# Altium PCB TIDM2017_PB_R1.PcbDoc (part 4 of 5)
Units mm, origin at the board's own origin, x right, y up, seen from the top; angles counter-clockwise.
Board outline 120 x 147.5 mm, 4 copper layers (Top Layer, L2, L3, Bottom Layer), stack 1.413 mm thick; 117 components, 53 nets, 3137 pads, 96 vias.
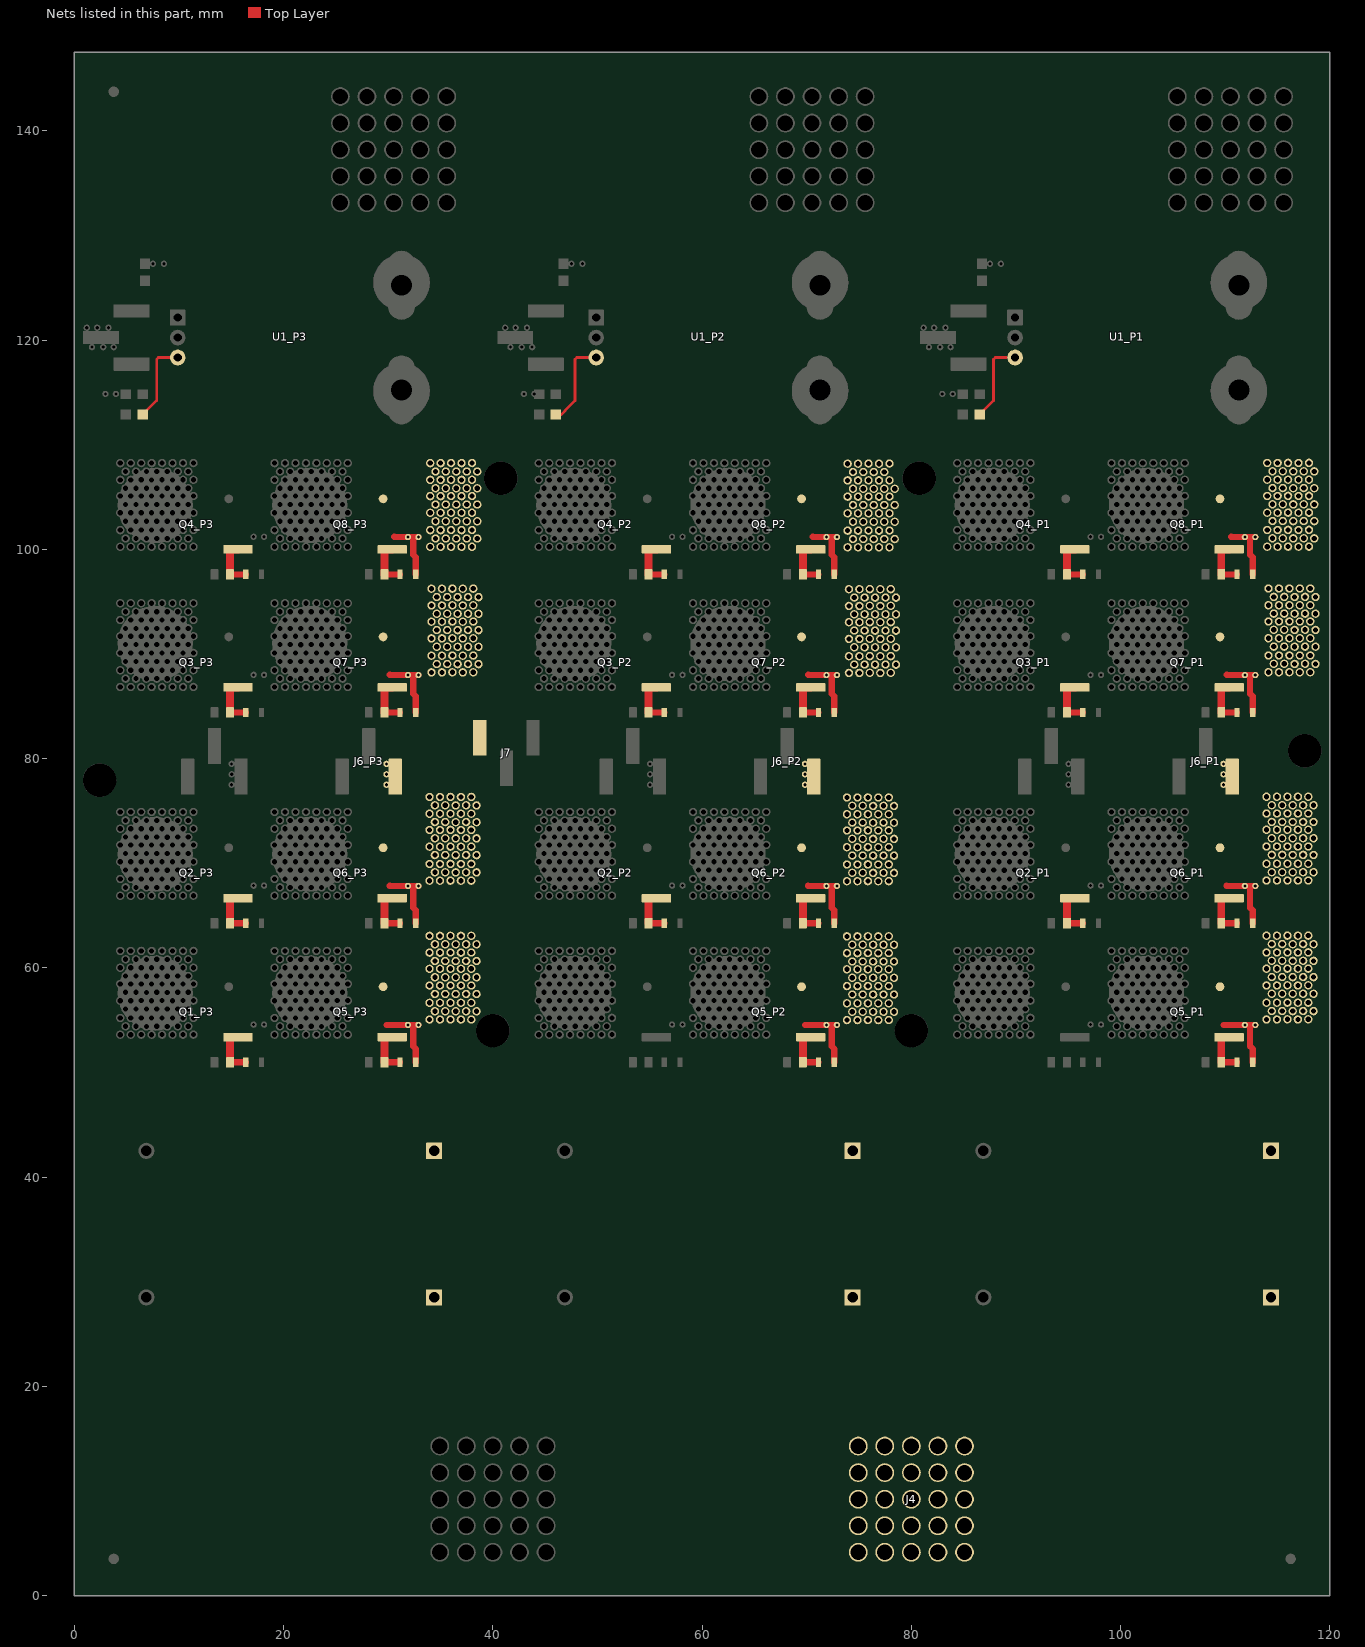
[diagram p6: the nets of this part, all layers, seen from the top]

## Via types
v1: diameter 0.8, hole 0.5, Top Layer to Bottom Layer, 96 vias

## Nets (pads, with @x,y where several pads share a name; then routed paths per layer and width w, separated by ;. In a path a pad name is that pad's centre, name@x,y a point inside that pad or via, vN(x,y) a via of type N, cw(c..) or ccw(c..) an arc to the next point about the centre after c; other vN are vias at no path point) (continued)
NetQ1_P3_1: Q1_P3.1 R1_P3.2 R5_P3.2 | length 4.6
  Top Layer w0.6: R1_P3.2@14.876,50.975 R5_P3.2@16.376,50.975
  Top Layer w0.75: R1_P3.2@14.876,50.975 14.876,53.347 14.901,53.372 Q1_P3.1@15.626,53.372
NetQ2_P1_1: Q2_P1.1 R2_P1.2 R6_P1.2 | length 4.6
  Top Layer w0.6: R2_P1.2@94.876,64.258 R6_P1.2@96.376,64.258
  Top Layer w0.75: R2_P1.2@94.876,64.258 94.876,66.63 94.901,66.655 Q2_P1.1@95.626,66.655
NetQ2_P2_1: Q2_P2.1 R2_P2.2 R6_P2.2 | length 4.6
  Top Layer w0.6: R2_P2.2@54.876,64.258 R6_P2.2@56.376,64.258
  Top Layer w0.75: R2_P2.2@54.876,64.258 54.876,66.63 54.901,66.655 Q2_P2.1@55.626,66.655
NetQ2_P3_1: Q2_P3.1 R2_P3.2 R6_P3.2 | length 4.6
  Top Layer w0.6: R2_P3.2@14.876,64.258 R6_P3.2@16.376,64.258
  Top Layer w0.75: R2_P3.2@14.876,64.258 14.876,66.63 14.901,66.655 Q2_P3.1@15.626,66.655
NetQ3_P1_1: Q3_P1.1 R3_P1.2 R7_P1.2 | length 4.6
  Top Layer w0.6: R3_P1.2@94.876,84.411 R7_P1.2@96.376,84.411
  Top Layer w0.75: R3_P1.2@94.876,84.411 94.876,86.783 94.901,86.808 Q3_P1.1@95.626,86.808
NetQ3_P2_1: Q3_P2.1 R3_P2.2 R7_P2.2 | length 4.6
  Top Layer w0.6: R3_P2.2@54.876,84.411 R7_P2.2@56.376,84.411
  Top Layer w0.75: R3_P2.2@54.876,84.411 54.876,86.783 54.901,86.808 Q3_P2.1@55.626,86.808
NetQ3_P3_1: Q3_P3.1 R3_P3.2 R7_P3.2 | length 4.6
  Top Layer w0.6: R3_P3.2@14.876,84.411 R7_P3.2@16.376,84.411
  Top Layer w0.75: R3_P3.2@14.876,84.411 14.876,86.783 14.901,86.808 Q3_P3.1@15.626,86.808
NetQ4_P1_1: Q4_P1.1 R4_P1.2 R8_P1.2 | length 4.6
  Top Layer w0.6: R4_P1.2@94.876,97.606 R8_P1.2@96.376,97.606
  Top Layer w0.75: R4_P1.2@94.876,97.606 94.876,99.978 94.901,100.003 Q4_P1.1@95.626,100.003
NetQ4_P2_1: Q4_P2.1 R4_P2.2 R8_P2.2 | length 4.6
  Top Layer w0.6: R4_P2.2@54.876,97.606 R8_P2.2@56.376,97.606
  Top Layer w0.75: R4_P2.2@54.876,97.606 54.876,99.978 54.901,100.003 Q4_P2.1@55.626,100.003
NetQ4_P3_1: Q4_P3.1 R4_P3.2 R8_P3.2 | length 4.6
  Top Layer w0.6: R4_P3.2@14.876,97.606 R8_P3.2@16.376,97.606
  Top Layer w0.75: R4_P3.2@14.876,97.606 14.876,99.978 14.901,100.003 Q4_P3.1@15.626,100.003
NetQ5_P1_1: Q5_P1.1 R9_P1.2 R13_P1.2 | length 4.6
  Top Layer w0.6: R9_P1.2@109.626,50.975 R13_P1.2@111.126,50.975
  Top Layer w0.75: R9_P1.2@109.626,50.975 109.626,53.347 109.651,53.372 Q5_P1.1@110.376,53.372
NetQ5_P2_1: Q5_P2.1 R9_P2.2 R13_P2.2 | length 4.6
  Top Layer w0.6: R9_P2.2@69.626,50.975 R13_P2.2@71.126,50.975
  Top Layer w0.75: R9_P2.2@69.626,50.975 69.626,53.347 69.651,53.372 Q5_P2.1@70.376,53.372
NetQ5_P3_1: Q5_P3.1 R9_P3.2 R13_P3.2 | length 4.6
  Top Layer w0.6: R9_P3.2@29.626,50.975 R13_P3.2@31.126,50.975
  Top Layer w0.75: R9_P3.2@29.626,50.975 29.626,53.347 29.651,53.372 Q5_P3.1@30.376,53.372
NetQ6_P1_1: Q6_P1.1 R10_P1.2 R14_P1.2 | length 4.6
  Top Layer w0.6: R10_P1.2@109.626,64.258 R14_P1.2@111.126,64.258
  Top Layer w0.75: R10_P1.2@109.626,64.258 109.626,66.63 109.651,66.655 Q6_P1.1@110.376,66.655
NetQ6_P2_1: Q6_P2.1 R10_P2.2 R14_P2.2 | length 4.6
  Top Layer w0.6: R10_P2.2@69.626,64.258 R14_P2.2@71.126,64.258
  Top Layer w0.75: R10_P2.2@69.626,64.258 69.626,66.63 69.651,66.655 Q6_P2.1@70.376,66.655
NetQ6_P3_1: Q6_P3.1 R10_P3.2 R14_P3.2 | length 4.6
  Top Layer w0.6: R10_P3.2@29.626,64.258 R14_P3.2@31.126,64.258
  Top Layer w0.75: R10_P3.2@29.626,64.258 29.626,66.63 29.651,66.655 Q6_P3.1@30.376,66.655
NetQ7_P1_1: Q7_P1.1 R11_P1.2 R15_P1.2 | length 4.6
  Top Layer w0.6: R11_P1.2@109.626,84.411 R15_P1.2@111.126,84.411
  Top Layer w0.75: R11_P1.2@109.626,84.411 109.626,86.783 109.651,86.808 Q7_P1.1@110.376,86.808
NetQ7_P2_1: Q7_P2.1 R11_P2.2 R15_P2.2 | length 4.6
  Top Layer w0.6: R11_P2.2@69.626,84.411 R15_P2.2@71.126,84.411
  Top Layer w0.75: R11_P2.2@69.626,84.411 69.626,86.783 69.651,86.808 Q7_P2.1@70.376,86.808
NetQ7_P3_1: Q7_P3.1 R11_P3.2 R15_P3.2 | length 4.6
  Top Layer w0.6: R11_P3.2@29.626,84.411 R15_P3.2@31.126,84.411
  Top Layer w0.75: R11_P3.2@29.626,84.411 29.626,86.783 29.651,86.808 Q7_P3.1@30.376,86.808
NetQ8_P1_1: Q8_P1.1 R12_P1.2 R16_P1.2 | length 4.6
  Top Layer w0.6: R12_P1.2@109.626,97.606 R16_P1.2@111.126,97.606
  Top Layer w0.75: R12_P1.2@109.626,97.606 109.626,99.978 109.651,100.003 Q8_P1.1@110.376,100.003
NetQ8_P2_1: Q8_P2.1 R12_P2.2 R16_P2.2 | length 4.6
  Top Layer w0.6: R12_P2.2@69.626,97.606 R16_P2.2@71.126,97.606
  Top Layer w0.75: R12_P2.2@69.626,97.606 69.626,99.978 69.651,100.003 Q8_P2.1@70.376,100.003
NetQ8_P3_1: Q8_P3.1 R12_P3.2 R16_P3.2 | length 4.6
  Top Layer w0.6: R12_P3.2@29.626,97.606 R16_P3.2@31.126,97.606
  Top Layer w0.75: R12_P3.2@29.626,97.606 29.626,99.978 29.651,100.003 Q8_P3.1@30.376,100.003
NetR17_P1_2: R17_P1.2 U1_P1.3 | length 7.2
  Top Layer w0.25: R17_P1.2@86.52,112.886 86.545,112.886 86.895,113.236 86.895,113.261 87.85,114.216 87.85,118.167 88.023,118.34 89.092,118.34
NetR17_P2_2: R17_P2.2 U1_P2.3 | length 7.2
  Top Layer w0.25: 46.52,112.886 46.545,112.886 46.895,113.236 46.895,113.261 47.85,114.216 47.85,118.167 48.023,118.34 49.092,118.34
NetR17_P3_2: R17_P3.2 U1_P3.3 | length 7.2
  Top Layer w0.25: R17_P3.2@6.52,112.886 6.545,112.886 6.895,113.236 6.895,113.261 7.85,114.216 7.85,118.167 8.023,118.34 9.092,118.34
S_LS_P1: C1_P1.1 C1_P2.1 C1_P3.1 C2_P1.1 C2_P2.1 C2_P3.1 J4.1 J6_P1.1 J6_P2.1 J6_P3.1 J7.1 pad.2@29.826,77.5 pad.2@29.826,78.5 pad.2@29.826,79.5 pad.2@31.876,54.547 pad.2@31.876,67.83 pad.2@31.876,87.983 pad.2@31.876,101.178 pad.2@32.876,54.547 pad.2@32.876,67.83 pad.2@32.876,87.983 pad.2@32.876,101.178 pad.2@33.939,55.054 pad.2@33.939,56.654 pad.2@33.939,58.304 pad.2@33.939,59.904 pad.2@33.939,61.457 pad.2@33.939,63.057 pad.2@33.939,68.332 pad.2@33.939,69.932 pad.2@33.939,71.582 pad.2@33.939,73.182 pad.2@33.939,74.735 pad.2@33.939,76.335 pad.2@34.001,100.242 pad.2@34.001,101.842 pad.2@34.001,103.492 pad.2@34.001,105.092 pad.2@34.001,106.644 pad.2@34.001,108.244 pad.2@34.126,88.242 pad.2@34.126,89.842 pad.2@34.126,91.492 pad.2@34.126,93.092 pad.2@34.126,94.644 pad.2@34.126,96.244 pad.2@34.452,55.852 pad.2@34.452,57.502 pad.2@34.452,59.102 pad.2@34.452,60.655 pad.2@34.452,62.255 pad.2@34.452,69.13 pad.2@34.452,70.78 pad.2@34.452,72.38 pad.2@34.452,73.933 pad.2@34.452,75.533 pad.2@34.514,101.04 pad.2@34.514,102.69 pad.2@34.514,104.29 pad.2@34.514,105.843 pad.2@34.514,107.443 pad.2@34.639,89.04 pad.2@34.639,90.69 pad.2@34.639,92.29 pad.2@34.639,93.843 pad.2@34.639,95.443 pad.2@34.939,55.054 pad.2@34.939,56.654 pad.2@34.939,58.304 pad.2@34.939,59.904 pad.2@34.939,61.457 pad.2@34.939,63.057 pad.2@34.939,68.332 pad.2@34.939,69.932 pad.2@34.939,71.582 pad.2@34.939,73.182 pad.2@34.939,74.735 pad.2@34.939,76.335 pad.2@35.001,100.242 pad.2@35.001,101.842 pad.2@35.001,103.492 pad.2@35.001,105.092 pad.2@35.001,106.644 pad.2@35.001,108.244 pad.2@35.126,88.242 pad.2@35.126,89.842 pad.2@35.126,91.492 pad.2@35.126,93.092 pad.2@35.126,94.644 pad.2@35.126,96.244 pad.2@35.439,55.852 pad.2@35.439,57.502 pad.2@35.439,59.102 pad.2@35.439,60.655 pad.2@35.439,62.255 pad.2@35.439,69.13 pad.2@35.439,70.78 pad.2@35.439,72.38 pad.2@35.439,73.933 pad.2@35.439,75.533 pad.2@35.501,101.04 pad.2@35.501,102.69 pad.2@35.501,104.29 pad.2@35.501,105.843 pad.2@35.501,107.443 pad.2@35.626,89.04 pad.2@35.626,90.69 pad.2@35.626,92.29 pad.2@35.626,93.843 pad.2@35.626,95.443 pad.2@35.939,55.059 pad.2@35.939,56.659 pad.2@35.939,58.309 pad.2@35.939,59.909 pad.2@35.939,61.462 pad.2@35.939,63.062 pad.2@35.939,68.337 pad.2@35.939,69.937 pad.2@35.939,71.587 pad.2@35.939,73.187 pad.2@35.939,74.74 pad.2@35.939,76.34 pad.2@36.001,100.247 pad.2@36.001,101.847 pad.2@36.001,103.497 pad.2@36.001,105.097 pad.2@36.001,106.65 pad.2@36.001,108.25 pad.2@36.126,88.247 pad.2@36.126,89.847 pad.2@36.126,91.497 pad.2@36.126,93.097 pad.2@36.126,94.65 pad.2@36.126,96.25 pad.2@36.439,55.847 pad.2@36.439,57.497 pad.2@36.439,59.097 pad.2@36.439,60.649 pad.2@36.439,62.249 pad.2@36.439,69.125 pad.2@36.439,70.775 pad.2@36.439,72.375 pad.2@36.439,73.927 pad.2@36.439,75.527 pad.2@36.501,101.035 pad.2@36.501,102.685 pad.2@36.501,104.285 pad.2@36.501,105.837 pad.2@36.501,107.437 pad.2@36.626,89.035 pad.2@36.626,90.685 pad.2@36.626,92.285 pad.2@36.626,93.837 pad.2@36.626,95.437 pad.2@36.939,55.054 pad.2@36.939,56.654 pad.2@36.939,58.304 pad.2@36.939,59.904 pad.2@36.939,61.457 pad.2@36.939,63.057 pad.2@36.939,68.332 pad.2@36.939,69.932 pad.2@36.939,71.582 pad.2@36.939,73.182 pad.2@36.939,74.735 pad.2@36.939,76.335 pad.2@37.001,100.242 pad.2@37.001,101.842 pad.2@37.001,103.492 pad.2@37.001,105.092 pad.2@37.001,106.644 pad.2@37.001,108.244 pad.2@37.126,88.242 pad.2@37.126,89.842 pad.2@37.126,91.492 pad.2@37.126,93.092 pad.2@37.126,94.644 pad.2@37.126,96.244 pad.2@37.439,55.852 pad.2@37.439,57.502 pad.2@37.439,59.102 pad.2@37.439,60.655 pad.2@37.439,62.255 pad.2@37.439,69.13 pad.2@37.439,70.78 pad.2@37.439,72.38 pad.2@37.439,73.933 pad.2@37.439,75.533 pad.2@37.501,101.04 pad.2@37.501,102.69 pad.2@37.501,104.29 pad.2@37.501,105.843 pad.2@37.501,107.443 pad.2@37.626,89.04 pad.2@37.626,90.69 pad.2@37.626,92.29 pad.2@37.626,93.843 pad.2@37.626,95.443 pad.2@37.939,55.059 pad.2@37.939,56.659 pad.2@37.939,58.309 pad.2@37.939,59.909 pad.2@37.939,61.462 pad.2@37.939,63.062 pad.2@37.939,68.337 pad.2@37.939,69.937 pad.2@37.939,71.587 pad.2@37.939,73.187 pad.2@37.939,74.74 pad.2@37.939,76.34 pad.2@38.001,100.247 pad.2@38.001,101.847 pad.2@38.001,103.497 pad.2@38.001,105.097 pad.2@38.001,106.65 pad.2@38.001,108.25 pad.2@38.126,88.247 pad.2@38.126,89.847 pad.2@38.126,91.497 pad.2@38.126,93.097 pad.2@38.126,94.65 pad.2@38.126,96.25 pad.2@38.439,55.847 pad.2@38.439,57.497 pad.2@38.439,59.097 pad.2@38.439,60.649 pad.2@38.439,62.249 pad.2@38.439,69.125 pad.2@38.439,70.775 pad.2@38.439,72.375 pad.2@38.439,73.927 pad.2@38.439,75.527 pad.2@38.501,101.035 pad.2@38.501,102.685 pad.2@38.501,104.285 pad.2@38.501,105.837 pad.2@38.501,107.437 pad.2@38.626,89.035 pad.2@38.626,90.685 pad.2@38.626,92.285 pad.2@38.626,93.837 pad.2@38.626,95.437 pad.2@69.826,77.5 pad.2@69.826,78.5 pad.2@69.826,79.5 pad.2@71.876,54.547 pad.2@71.876,67.83 pad.2@71.876,87.983 pad.2@71.876,101.178 pad.2@72.876,54.547 pad.2@72.876,67.83 pad.2@72.876,87.983 pad.2@72.876,101.178 pad.2@73.842,55.005 pad.2@73.842,56.605 pad.2@73.842,58.255 pad.2@73.842,59.855 pad.2@73.842,61.408 pad.2@73.842,63.008 pad.2@73.842,68.283 pad.2@73.842,69.883 pad.2@73.842,71.533 pad.2@73.842,73.133 pad.2@73.842,74.686 pad.2@73.842,76.286 pad.2@73.904,100.193 pad.2@73.904,101.793 pad.2@73.904,103.443 pad.2@73.904,105.043 pad.2@73.904,106.596 pad.2@73.904,108.196 pad.2@74.029,88.193 pad.2@74.029,89.793 pad.2@74.029,91.443 pad.2@74.029,93.043 pad.2@74.029,94.596 pad.2@74.029,96.196 pad.2@74.355,55.804 pad.2@74.355,57.454 pad.2@74.355,59.054 pad.2@74.355,60.606 pad.2@74.355,62.206 pad.2@74.355,69.082 pad.2@74.355,70.732 pad.2@74.355,72.332 pad.2@74.355,73.884 pad.2@74.355,75.484 pad.2@74.417,100.992 pad.2@74.417,102.642 pad.2@74.417,104.242 pad.2@74.417,105.794 pad.2@74.417,107.394 pad.2@74.542,88.992 pad.2@74.542,90.642 pad.2@74.542,92.242 pad.2@74.542,93.794 pad.2@74.542,95.394 pad.2@74.842,55.005 pad.2@74.842,56.605 pad.2@74.842,58.255 pad.2@74.842,59.855 pad.2@74.842,61.408 pad.2@74.842,63.008 pad.2@74.842,68.283 pad.2@74.842,69.883 pad.2@74.842,71.533 pad.2@74.842,73.133 pad.2@74.842,74.686 pad.2@74.842,76.286 pad.2@74.904,100.193 pad.2@74.904,101.793 pad.2@74.904,103.443 pad.2@74.904,105.043 pad.2@74.904,106.596 pad.2@74.904,108.196 pad.2@75.029,88.193 pad.2@75.029,89.793 pad.2@75.029,91.443 pad.2@75.029,93.043 pad.2@75.029,94.596 pad.2@75.029,96.196 pad.2@75.342,55.804 pad.2@75.342,57.454 pad.2@75.342,59.054 pad.2@75.342,60.606 pad.2@75.342,62.206 pad.2@75.342,69.082 pad.2@75.342,70.732 pad.2@75.342,72.332 pad.2@75.342,73.884 pad.2@75.342,75.484 pad.2@75.404,100.992 pad.2@75.404,102.642 pad.2@75.404,104.242 pad.2@75.404,105.794 pad.2@75.404,107.394 pad.2@75.529,88.992 pad.2@75.529,90.642 pad.2@75.529,92.242 pad.2@75.529,93.794 pad.2@75.529,95.394 pad.2@75.842,55.011 pad.2@75.842,56.611 pad.2@75.842,58.261 pad.2@75.842,59.861 pad.2@75.842,61.414 pad.2@75.842,63.014 pad.2@75.842,68.289 pad.2@75.842,69.889 pad.2@75.842,71.539 pad.2@75.842,73.139 pad.2@75.842,74.692 pad.2@75.842,76.292 pad.2@75.904,100.199 pad.2@75.904,101.799 pad.2@75.904,103.449 pad.2@75.904,105.049 pad.2@75.904,106.602 pad.2@75.904,108.202 pad.2@76.029,88.199 pad.2@76.029,89.799 pad.2@76.029,91.449 pad.2@76.029,93.049 pad.2@76.029,94.602 pad.2@76.029,96.202 pad.2@76.342,55.798 pad.2@76.342,57.448 pad.2@76.342,59.048 pad.2@76.342,60.601 pad.2@76.342,62.201 pad.2@76.342,69.076 pad.2@76.342,70.726 pad.2@76.342,72.326 pad.2@76.342,73.879 pad.2@76.342,75.479 pad.2@76.404,100.986 pad.2@76.404,102.636 pad.2@76.404,104.236 pad.2@76.404,105.789 pad.2@76.404,107.389 pad.2@76.529,88.986 pad.2@76.529,90.636 pad.2@76.529,92.236 pad.2@76.529,93.789 pad.2@76.529,95.389 pad.2@76.842,55.005 pad.2@76.842,56.605 pad.2@76.842,58.255 pad.2@76.842,59.855 pad.2@76.842,61.408 pad.2@76.842,63.008 pad.2@76.842,68.283 pad.2@76.842,69.883 pad.2@76.842,71.533 pad.2@76.842,73.133 pad.2@76.842,74.686 pad.2@76.842,76.286 pad.2@76.904,100.193 pad.2@76.904,101.793 pad.2@76.904,103.443 pad.2@76.904,105.043 pad.2@76.904,106.596 pad.2@76.904,108.196 pad.2@77.029,88.193 pad.2@77.029,89.793 pad.2@77.029,91.443 pad.2@77.029,93.043 pad.2@77.029,94.596 pad.2@77.029,96.196 pad.2@77.342,55.804 pad.2@77.342,57.454 pad.2@77.342,59.054 pad.2@77.342,60.606 pad.2@77.342,62.206 pad.2@77.342,69.082 pad.2@77.342,70.732 pad.2@77.342,72.332 pad.2@77.342,73.884 pad.2@77.342,75.484 pad.2@77.404,100.992 pad.2@77.404,102.642 pad.2@77.404,104.242 pad.2@77.404,105.794 pad.2@77.404,107.394 pad.2@77.529,88.992 pad.2@77.529,90.642 pad.2@77.529,92.242 pad.2@77.529,93.794 pad.2@77.529,95.394 pad.2@77.842,55.011 pad.2@77.842,56.611 pad.2@77.842,58.261 pad.2@77.842,59.861 pad.2@77.842,61.414 pad.2@77.842,63.014 pad.2@77.842,68.289 pad.2@77.842,69.889 pad.2@77.842,71.539 pad.2@77.842,73.139 pad.2@77.842,74.692 pad.2@77.842,76.292 pad.2@77.904,100.199 pad.2@77.904,101.799 pad.2@77.904,103.449 pad.2@77.904,105.049 pad.2@77.904,106.602 pad.2@77.904,108.202 pad.2@78.029,88.199 pad.2@78.029,89.799 pad.2@78.029,91.449 pad.2@78.029,93.049 pad.2@78.029,94.602 pad.2@78.029,96.202 pad.2@78.342,55.798 pad.2@78.342,57.448 pad.2@78.342,59.048 pad.2@78.342,60.601 pad.2@78.342,62.201 pad.2@78.342,69.076 pad.2@78.342,70.726 pad.2@78.342,72.326 pad.2@78.342,73.879 pad.2@78.342,75.479 pad.2@78.404,100.986 pad.2@78.404,102.636 pad.2@78.404,104.236 pad.2@78.404,105.789 pad.2@78.529,88.986 pad.2@78.529,90.636 pad.2@78.529,92.236 pad.2@78.529,93.789 pad.2@78.529,95.389 pad.2@109.826,77.5 pad.2@109.826,78.5 pad.2@109.826,79.5 pad.2@111.876,54.547 pad.2@111.876,67.83 pad.2@111.876,87.983 pad.2@111.876,101.178 pad.2@112.876,54.547 pad.2@112.876,67.83 pad.2@112.876,87.983 pad.2@112.876,101.178 pad.2@113.944,55.071 pad.2@113.944,56.671 pad.2@113.944,58.321 pad.2@113.944,59.921 pad.2@113.944,61.474 pad.2@113.944,63.074 pad.2@113.944,68.349 pad.2@113.944,69.949 pad.2@113.944,71.599 pad.2@113.944,73.199 pad.2@113.944,74.752 pad.2@113.944,76.352 pad.2@114.006,100.259 pad.2@114.006,101.859 pad.2@114.006,103.509 pad.2@114.006,105.109 pad.2@114.006,106.661 pad.2@114.006,108.261 pad.2@114.131,88.259 pad.2@114.131,89.859 pad.2@114.131,91.509 pad.2@114.131,93.109 pad.2@114.131,94.661 pad.2@114.131,96.261 pad.2@114.457,55.869 pad.2@114.457,57.519 pad.2@114.457,59.119 pad.2@114.457,60.672 pad.2@114.457,62.272 pad.2@114.457,69.147 pad.2@114.457,70.797 pad.2@114.457,72.397 pad.2@114.457,73.95 pad.2@114.457,75.55 pad.2@114.519,101.057 pad.2@114.519,102.707 pad.2@114.519,104.307 pad.2@114.519,105.86 pad.2@114.519,107.46 pad.2@114.644,89.057 pad.2@114.644,90.707 pad.2@114.644,92.307 pad.2@114.644,93.86 pad.2@114.644,95.46 pad.2@114.944,55.071 pad.2@114.944,56.671 pad.2@114.944,58.321 pad.2@114.944,59.921 pad.2@114.944,61.474 pad.2@114.944,63.074 pad.2@114.944,68.349 pad.2@114.944,69.949 pad.2@114.944,71.599 pad.2@114.944,73.199 pad.2@114.944,74.752 pad.2@114.944,76.352 pad.2@115.006,100.259 pad.2@115.006,101.859 pad.2@115.006,103.509 pad.2@115.006,105.109 pad.2@115.006,106.661 pad.2@115.006,108.261 pad.2@115.131,88.259 pad.2@115.131,89.859 pad.2@115.131,91.509 pad.2@115.131,93.109 pad.2@115.131,94.661 pad.2@115.131,96.261 pad.2@115.444,55.869 pad.2@115.444,57.519 pad.2@115.444,59.119 pad.2@115.444,60.672 pad.2@115.444,62.272 pad.2@115.444,69.147 pad.2@115.444,70.797 pad.2@115.444,72.397 pad.2@115.444,73.95 pad.2@115.444,75.55 pad.2@115.506,101.057 pad.2@115.506,102.707 pad.2@115.506,104.307 pad.2@115.506,105.86 pad.2@115.506,107.46 pad.2@115.631,89.057 pad.2@115.631,90.707 pad.2@115.631,92.307 pad.2@115.631,93.86 pad.2@115.631,95.46 pad.2@115.944,55.076 pad.2@115.944,56.676 pad.2@115.944,58.326 pad.2@115.944,59.926 pad.2@115.944,61.479 pad.2@115.944,63.079 pad.2@115.944,68.354 pad.2@115.944,69.954 pad.2@115.944,71.604 pad.2@115.944,73.204 pad.2@115.944,74.757 pad.2@115.944,76.357 pad.2@116.006,100.264 pad.2@116.006,101.864 pad.2@116.006,103.514 pad.2@116.006,105.114 pad.2@116.006,106.667 pad.2@116.006,108.267 pad.2@116.131,88.264 pad.2@116.131,89.864 pad.2@116.131,91.514 pad.2@116.131,93.114 pad.2@116.131,94.667 pad.2@116.131,96.267 pad.2@116.444,55.864 pad.2@116.444,57.514 pad.2@116.444,59.114 pad.2@116.444,60.666 pad.2@116.444,62.266 pad.2@116.444,69.142 pad.2@116.444,70.792 pad.2@116.444,72.392 pad.2@116.444,73.944 pad.2@116.444,75.544 pad.2@116.506,101.052 pad.2@116.506,102.702 pad.2@116.506,104.302 pad.2@116.506,105.854 pad.2@116.506,107.454 pad.2@116.631,89.052 pad.2@116.631,90.702 pad.2@116.631,92.302 pad.2@116.631,93.854 pad.2@116.631,95.454 pad.2@116.944,55.071 pad.2@116.944,56.671 pad.2@116.944,58.321 pad.2@116.944,59.921 pad.2@116.944,61.474 pad.2@116.944,63.074 pad.2@116.944,68.349 pad.2@116.944,69.949 pad.2@116.944,71.599 pad.2@116.944,73.199 pad.2@116.944,74.752 pad.2@116.944,76.352 pad.2@117.006,100.259 pad.2@117.006,101.859 pad.2@117.006,103.509 pad.2@117.006,105.109 pad.2@117.006,106.661 pad.2@117.006,108.261 pad.2@117.131,88.259 pad.2@117.131,89.859 pad.2@117.131,91.509 pad.2@117.131,93.109 pad.2@117.131,94.661 pad.2@117.131,96.261 pad.2@117.444,55.869 pad.2@117.444,57.519 pad.2@117.444,59.119 pad.2@117.444,60.672 pad.2@117.444,62.272 pad.2@117.444,69.147 pad.2@117.444,70.797 pad.2@117.444,72.397 pad.2@117.444,73.95 pad.2@117.444,75.55 pad.2@117.506,101.057 pad.2@117.506,102.707 pad.2@117.506,104.307 pad.2@117.506,105.86 pad.2@117.506,107.46 pad.2@117.631,89.057 pad.2@117.631,90.707 pad.2@117.631,92.307 pad.2@117.631,93.86 pad.2@117.631,95.46 pad.2@117.944,55.076 pad.2@117.944,56.676 pad.2@117.944,58.326 pad.2@117.944,59.926 pad.2@117.944,61.479 pad.2@117.944,63.079 pad.2@117.944,68.354 pad.2@117.944,69.954 pad.2@117.944,71.604 pad.2@117.944,73.204 pad.2@117.944,74.757 pad.2@117.944,76.357 pad.2@118.006,100.264 pad.2@118.006,101.864 pad.2@118.006,103.514 pad.2@118.006,105.114 pad.2@118.006,106.667 pad.2@118.006,108.267 pad.2@118.131,88.264 pad.2@118.131,89.864 pad.2@118.131,91.514 pad.2@118.131,93.114 pad.2@118.131,94.667 pad.2@118.131,96.267 pad.2@118.444,55.864 pad.2@118.444,57.514 pad.2@118.444,59.114 pad.2@118.444,60.666 pad.2@118.444,62.266 pad.2@118.444,69.142 pad.2@118.444,70.792 pad.2@118.444,72.392 pad.2@118.444,73.944 pad.2@118.444,75.544 pad.2@118.506,101.052 pad.2@118.506,102.702 pad.2@118.506,104.302 pad.2@118.506,105.854 pad.2@118.506,107.454 pad.2@118.631,89.052 pad.2@118.631,90.702 pad.2@118.631,92.302 pad.2@118.631,93.854 pad.2@118.631,95.454 Q5_P1.2-3-4-5-6-7-8 Q5_P2.2-3-4-5-6-7-8 Q5_P3.2-3-4-5-6-7-8 Q6_P1.2-3-4-5-6-7-8 Q6_P2.2-3-4-5-6-7-8 Q6_P3.2-3-4-5-6-7-8 Q7_P1.2-3-4-5-6-7-8 Q7_P2.2-3-4-5-6-7-8 Q7_P3.2-3-4-5-6-7-8 Q8_P1.2-3-4-5-6-7-8 Q8_P2.2-3-4-5-6-7-8 Q8_P3.2-3-4-5-6-7-8 R13_P1.1 R13_P2.1 R13_P3.1 R14_P1.1 R14_P2.1 R14_P3.1 R15_P1.1 R15_P2.1 R15_P3.1 R16_P1.1 R16_P2.1 R16_P3.1 | length 76.7
  Top Layer w0.6: 29.826,54.547 pad.2@31.876,54.547 32.376,54.547 ; 30.126,67.855 30.151,67.83 pad.2@31.876,67.83 32.376,67.83 ; 30.151,88.008 30.176,87.983 pad.2@31.876,87.983 32.376,87.983 ; 30.576,101.203 30.601,101.178 pad.2@31.876,101.178 32.376,101.178 ; R13_P3.1@32.626,50.975 32.626,52.25 32.376,52.5 32.376,54.547 ; R14_P3.1@32.626,64.258 32.626,65.5 32.376,65.75 32.376,67.83 ; R15_P3.1@32.626,84.411 32.626,85.958 32.376,86.208 32.376,87.983 ; R16_P3.1@32.626,97.606 32.626,99.25 32.376,99.5 32.376,101.178 ; pad.2@32.876,54.547 32.376,54.547 ; pad.2@32.876,67.83 32.376,67.83 ; pad.2@32.876,87.983 32.376,87.983 ; pad.2@32.876,101.178 32.376,101.178 ; 69.826,54.547 pad.2@71.876,54.547 72.376,54.547 ; 70.126,67.855 70.151,67.83 pad.2@71.876,67.83 72.376,67.83 ; 70.151,88.008 70.176,87.983 pad.2@71.876,87.983 72.376,87.983 ; 70.576,101.203 70.601,101.178 pad.2@71.876,101.178 72.376,101.178 ; R13_P2.1@72.626,50.975 72.626,52.25 72.376,52.5 72.376,54.547 ; R14_P2.1@72.626,64.258 72.626,65.5 72.376,65.75 72.376,67.83 ; R15_P2.1@72.626,84.411 72.626,85.958 72.376,86.208 72.376,87.983 ; R16_P2.1@72.626,97.606 72.626,99.25 72.376,99.5 72.376,101.178 ; pad.2@72.876,54.547 72.376,54.547 ; pad.2@72.876,67.83 72.376,67.83 ; pad.2@72.876,87.983 72.376,87.983 ; pad.2@72.876,101.178 72.376,101.178 ; 109.826,54.547 pad.2@111.876,54.547 112.376,54.547 ; 110.126,67.855 110.151,67.83 pad.2@111.876,67.83 112.376,67.83 ; 110.151,88.008 110.176,87.983 pad.2@111.876,87.983 112.376,87.983 ; 110.576,101.203 110.601,101.178 pad.2@111.876,101.178 112.376,101.178 ; R13_P1.1@112.626,50.975 112.626,52.25 112.376,52.5 112.376,54.547 ; R14_P1.1@112.626,64.258 112.626,65.5 112.376,65.75 112.376,67.83 ; R15_P1.1@112.626,84.411 112.626,85.958 112.376,86.208 112.376,87.983 ; R16_P1.1@112.626,97.606 112.626,99.25 112.376,99.5 112.376,101.178 ; pad.2@112.876,54.547 112.376,54.547 ; pad.2@112.876,67.83 112.376,67.83 ; pad.2@112.876,87.983 112.376,87.983 ; pad.2@112.876,101.178 112.376,101.178
pads on no net: FID1.1 FID2.1 FID3.1 LBL1.0

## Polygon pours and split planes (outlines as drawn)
D_LS_P3 on L2 "L2_D_LS_P3_P037" (solid, remove dead copper, pour order 37): 18.376,101.75 18.376,99.5 14.126,99.5 14.126,88.5 18.376,88.5 18.376,86.25 14.126,86.25 14.126,80.25 17.376,80.25 17.126,80 17.126,76.25 14.126,76.25 14.126,68.5 18.376,68.5 18.376,66 14.126,66 14.126,55 18.376,55 18.376,52.75 12.626,52.75 12.626,54.25 12.626,101.75
D_LS_P2 on L2 "L2_D_LS_P2_P038" (solid, remove dead copper, pour order 38): 58.376,101.75 58.376,99.5 54.126,99.5 54.126,88.5 58.376,88.5 58.376,86.25 54.126,86.25 54.126,80.25 57.376,80.25 57.126,80 57.126,76.25 54.126,76.25 54.126,68.5 58.376,68.5 58.376,66 54.126,66 54.126,55 58.376,55 58.376,52.75 52.626,52.75 52.626,54.25 52.626,101.75
D_LS_P1 on L2 "L2_D_LS_P1_P039" (solid, remove dead copper, pour order 39): 98.376,101.75 98.376,99.5 94.126,99.5 94.126,88.5 98.376,88.5 98.376,86.25 94.126,86.25 94.126,80.25 97.376,80.25 97.126,80 97.126,76.25 94.126,76.25 94.126,68.5 98.376,68.5 98.376,66 94.126,66 94.126,55 98.376,55 98.376,52.75 92.626,52.75 92.626,54.25 92.626,101.75
S_LS_P1 on L2 "L2_S_LS_P1_P043" (solid, remove dead copper, pour order 43): 33.126,101.75 33.126,99.5 28.876,99.5 28.876,88.5 33.126,88.5 33.126,86.25 28.876,86.25 28.876,80.25 32.126,80.25 31.876,80 31.876,76.25 28.876,76.25 28.876,68.5 33.126,68.5 33.126,66 28.876,66 28.876,55 33.126,55 33.126,52.75 27.376,52.75 27.376,54.25 27.376,101.75
S_LS_P1 on L2 "L2_S_LS_P1_P044" (solid, remove dead copper, pour order 44): 73.126,101.75 73.126,99.5 68.876,99.5 68.876,88.5 73.126,88.5 73.126,86.25 68.876,86.25 68.876,80.25 72.126,80.25 71.876,80 71.876,76.25 68.876,76.25 68.876,68.5 73.126,68.5 73.126,66 68.876,66 68.876,55 73.126,55 73.126,52.75 67.376,52.75 67.376,54.25 67.376,101.75
S_LS_P1 on L2 "L2_S_LS_P1_P045" (solid, remove dead copper, pour order 45): 113.126,101.75 113.126,99.5 108.876,99.5 108.876,88.5 113.126,88.5 113.126,86.25 108.876,86.25 108.876,80.25 112.126,80.25 111.876,80 111.876,76.25 108.876,76.25 108.876,68.5 113.126,68.5 113.126,66 108.876,66 108.876,55 113.126,55 113.126,52.75 107.376,52.75 107.376,54.25 107.376,101.75
NetC3_P3_2 on L2 "L2_NETC3_P3_2_P049" (solid, remove dead copper, pour order 49): 0.647,128.275 11.876,128.275 11.876,111.75 0.647,111.75
NetC3_P2_2 on L2 "L2_NETC3_P2_2_P050" (solid, remove dead copper, pour order 50): 40.647,128.275 51.876,128.275 51.876,111.75 40.647,111.75
NetC3_P1_2 on L2 "L2_NETC3_P1_2_P051" (solid, remove dead copper, pour order 51): 80.647,128.275 91.876,128.275 91.876,111.75 80.647,111.75
NetJ1_P3_1 on L2 "L2_NETJ1_P3_1_P064" (solid, remove dead copper, pour order 64): 37.5,145.011 37.5,120.75 23.5,120.75 23.5,120.95 23.5,145.011
NetJ1_P2_1 on L2 "L2_NETJ1_P2_1_P065" (solid, remove dead copper, pour order 65): 77.5,145.011 77.5,120.75 63.5,120.75 63.5,120.95 63.5,145.011
NetJ1_P1_1 on L2 "L2_NETJ1_P1_1_P066" (solid, remove dead copper, pour order 66): 117.5,145.011 117.5,120.75 103.5,120.75 103.5,120.95 103.5,145.011
D_HS_P1 on L2 "L2_D_HS_P1_P076" (solid, remove dead copper, pour order 76): 0.75,110 11.876,110 11.876,109.982 11.876,21.768 11.876,21.75 0.75,21.75
D_HS_P1 on L2 "L2_D_HS_P1_P077" (solid, remove dead copper, pour order 77): 40.75,110 51.876,110 51.876,109.982 51.876,21.768 51.876,21.75 40.75,21.75
D_HS_P1 on L2 "L2_D_HS_P1_P078" (solid, remove dead copper, pour order 78): 80.75,110 91.876,110 91.876,109.982 91.876,21.768 91.876,21.75 80.75,21.75
D_LS_P3 on L2 "L2_D_LS_P3_P100" (solid, remove dead copper, pour order 100): 37.5,119.75 37.5,109.5 28.717,109.5 26.75,107.533 26.75,52.25 18.5,52.25 18.5,55.211 14.25,55.211 14.25,65.751 14.126,65.875 18.5,65.875 18.5,68.75 14.25,68.75 14.25,76 17.376,76 17.376,80.5 14.25,80.5 14.25,86 18.5,86 18.5,88.75 14.25,88.75 14.25,99.25 18.5,99.25 18.5,101.847 14.25,101.847 14.25,113.75 20.25,119.75 37,119.75
D_LS_P2 on L2 "L2_D_LS_P2_P101" (solid, remove dead copper, pour order 101): 77.5,119.75 77.5,109.5 68.717,109.5 66.75,107.533 66.75,52.25 58.5,52.25 58.5,55.211 54.25,55.211 54.25,65.751 54.126,65.875 58.5,65.875 58.5,68.75 54.25,68.75 54.25,76 57.376,76 57.376,80.5 54.25,80.5 54.25,86 58.5,86 58.5,88.75 54.25,88.75 54.25,99.25 58.5,99.25 58.5,101.847 54.25,101.847 54.25,113.75 60.25,119.75 77,119.75
D_LS_P1 on L2 "L2_D_LS_P1_P102" (solid, remove dead copper, pour order 102): 117.5,119.75 117.5,109.5 108.717,109.5 106.75,107.533 106.75,52.25 98.5,52.25 98.5,55.211 94.25,55.211 94.25,65.751 94.126,65.875 98.5,65.875 98.5,68.75 94.25,68.75 94.25,76 97.376,76 97.376,80.5 94.25,80.5 94.25,86 98.5,86 98.5,88.75 94.25,88.75 94.25,99.25 98.5,99.25 98.5,101.847 94.25,101.847 94.25,113.75 100.25,119.75 117,119.75
D_HS_P1 on L2 "L2_D_HS_P1_P104" (solid, remove dead copper, pour order 104): 0.75,49.25 119.25,49.25 119.25,2 0.853,2 0.845,1.992
S_LS_P1 on L2 "L2_S_LS_P1_P108" (solid, remove dead copper, pour order 108): 28.876,109 39.5,109 39.5,49.5 33.341,49.5 33.341,55.188 33.364,55.211 29,55.211 29,63.5 33.341,63.5 33.341,68.727 33.364,68.75 29,68.75 29,75.75 29.25,76 32.376,76 32.376,80.5 29,80.5 29,86 33.25,86 33.25,88.75 29,88.75 29,96.75 33.5,96.75 33.5,101.847 28.876,101.847
S_LS_P1 on L2 "L2_S_LS_P1_P111" (solid, remove dead copper, pour order 111): 109,109.076 119.624,109.076 119.624,49.576 113.465,49.576 113.465,55.264 113.488,55.287 109.124,55.287 109.124,63.576 113.465,63.576 113.465,68.803 113.488,68.826 109.124,68.826 109.124,75.826 109.374,76.076 112.5,76.076 112.5,80.576 109.124,80.576 109.124,86.076 113.374,86.076 113.374,88.826 109.124,88.826 109.124,96.826 113.624,96.826 113.624,101.924 109,101.924
S_LS_P1 on L2 "L2_S_LS_P1_P112" (solid, remove dead copper, pour order 112): 68.876,109.076 79.5,109.076 79.5,49.576 73.341,49.576 73.341,55.264 73.364,55.287 69,55.287 69,63.576 73.341,63.576 73.341,68.803 73.364,68.826 69,68.826 69,75.826 69.25,76.076 72.376,76.076 72.376,80.576 69,80.576 69,86.076 73.25,86.076 73.25,88.826 69,88.826 69,96.826 73.5,96.826 73.5,101.924 68.876,101.924
+5V_P2 on Top Layer "TOP_LAYER_+5V_P2_P053" (solid, remove dead copper, pour order 53): 46.25,126.25 47.25,126.25 47.25,123.5 50,123.5 50,121.219 49.863,121.356 47.25,121.356 47.25,122.16 43.75,122.16 43.75,123.5 46.25,123.5
D_LS_P3 on Top Layer "TOP_LAYER_D_LS_P3_P040" (solid, remove dead copper, pour order 40): 14.626,80.25 14.707,80.25 17.126,80.25 17.126,76.25 17.026,76.25 14.626,76.25
D_LS_P2 on Top Layer "TOP_LAYER_D_LS_P2_P041" (solid, remove dead copper, pour order 41): 54.626,80.25 54.707,80.25 57.126,80.25 57.126,76.25 57.026,76.25 54.626,76.25
D_LS_P1 on Top Layer "TOP_LAYER_D_LS_P1_P042" (solid, remove dead copper, pour order 42): 94.626,80.25 94.707,80.25 97.126,80.25 97.126,76.25 97.026,76.25 94.626,76.25
S_LS_P1 on Top Layer "TOP_LAYER_S_LS_P1_P046" (solid, remove dead copper, pour order 46): 29.376,80.25 29.457,80.25 31.876,80.25 31.876,76.25 31.776,76.25 29.376,76.25
S_LS_P1 on Top Layer "TOP_LAYER_S_LS_P1_P047" (solid, remove dead copper, pour order 47): 69.376,80.25 69.457,80.25 71.876,80.25 71.876,76.25 71.776,76.25 69.376,76.25
S_LS_P1 on Top Layer "TOP_LAYER_S_LS_P1_P048" (solid, remove dead copper, pour order 48): 109.376,80.25 109.457,80.25 111.876,80.25 111.876,76.25 111.776,76.25 109.376,76.25
+5V_P3 on Top Layer "TOP_LAYER_+5V_P3_P052" (solid, remove dead copper, pour order 52): 6.25,126.25 7.25,126.25 7.25,123.5 10,123.5 10,121.219 9.863,121.356 7.25,121.356 7.25,122.16 3.75,122.16 3.75,123.5 6.25,123.5
NetJ1_P3_1 on Top Layer "TOP_LAYER_NETJ1_P3_1_P061" (solid, remove dead copper, pour order 61): 37.5,145 37.5,120.739 23.5,120.739 23.5,120.939 23.5,145
NetJ1_P2_1 on Top Layer "TOP_LAYER_NETJ1_P2_1_P062" (solid, remove dead copper, pour order 62): 77.5,145 77.5,120.739 63.5,120.739 63.5,120.939 63.5,145
NetJ1_P1_1 on Top Layer "TOP_LAYER_NETJ1_P1_1_P063" (solid, remove dead copper, pour order 63): 117.5,145 117.5,120.739 103.5,120.739 103.5,120.939 103.5,145
D_LS_P3 on Top Layer "TOP_LAYER_D_LS_P3_P073" (solid, remove dead copper, pour order 73): 14.226,113.726 20.25,119.75 37.5,119.75 37.5,109.496 28.708,109.496 26.75,107.538 26.75,52.25 18.476,52.25 18.476,55.172 18.398,55.25 14.226,55.25 14.226,63.5 18.476,63.5 18.476,68.5 14.226,68.5 14.226,75.905 17.376,75.905 17.376,82.5 18.476,83.6 18.476,88.808 14.226,88.808 14.226,96.65 18.476,96.65 18.476,102.003 14.229,102.003 14.226,102
D_LS_P2 on Top Layer "TOP_LAYER_D_LS_P2_P074" (solid, remove dead copper, pour order 74): 54.226,113.726 60.25,119.75 77.5,119.75 77.5,109.496 68.708,109.496 66.75,107.538 66.75,52.25 58.476,52.25 58.476,55.172 58.398,55.25 54.226,55.25 54.226,63.5 58.476,63.5 58.476,68.5 54.226,68.5 54.226,75.905 57.376,75.905 57.376,82.5 58.476,83.6 58.476,88.808 54.226,88.808 54.226,96.65 58.476,96.65 58.476,102.003 54.229,102.003 54.226,102
D_LS_P1 on Top Layer "TOP_LAYER_D_LS_P1_P075" (solid, remove dead copper, pour order 75): 94.226,113.726 100.25,119.75 117.5,119.75 117.5,109.496 108.708,109.496 106.75,107.538 106.75,52.25 98.476,52.25 98.476,55.172 98.398,55.25 94.226,55.25 94.226,63.5 98.476,63.5 98.476,68.5 94.226,68.5 94.226,75.905 97.376,75.905 97.376,82.5 98.476,83.6 98.476,88.808 94.226,88.808 94.226,96.65 98.476,96.65 98.476,102.003 94.229,102.003 94.226,102
D_HS_P1 on Top Layer "TOP_LAYER_D_HS_P1_P079" (solid, remove dead copper, pour order 79): 0.75,110 11.876,110 11.876,109.982 11.876,21.768 11.876,21.75 0.75,21.75
D_HS_P1 on Top Layer "TOP_LAYER_D_HS_P1_P080" (solid, remove dead copper, pour order 80): 40.75,110 51.876,110 51.876,109.982 51.876,21.768 51.876,21.75 40.75,21.75
D_HS_P1 on Top Layer "TOP_LAYER_D_HS_P1_P081" (solid, remove dead copper, pour order 81): 80.75,110 91.876,110 91.876,109.982 91.876,21.768 91.876,21.75 80.75,21.75
D_HS_P1 on Top Layer "TOP_LAYER_D_HS_P1_P103" (solid, remove dead copper, pour order 103): 0.75,49.25 119.25,49.25 119.25,2 0.853,2 0.845,1.992
S_LS_P1 on Top Layer "TOP_LAYER_S_LS_P1_P107" (solid, remove dead copper, pour order 107): 39.5,49.5 33,49.5 33,54.063 33.341,54.404 33.341,55.172 33.302,55.211 28.976,55.211 28.976,63.5 33.341,63.5 33.341,68.455 33.302,68.494 28.976,68.494 28.976,75.905 32.25,75.905 32.25,80.5 28.976,80.5 28.976,83.6 33.25,83.6 33.25,88.523 33.165,88.608 28.976,88.608 28.976,96.65 33.272,96.65 33.272,101.794 33.219,101.847 28.875,101.847 28.875,108.903 39.5,108.903
S_LS_P1 on Top Layer "TOP_LAYER_S_LS_P1_P109" (solid, remove dead copper, pour order 109): 79.403,49.452 72.903,49.452 72.903,54.014 73.244,54.355 73.244,55.123 73.205,55.162 68.879,55.162 68.879,63.452 73.244,63.452 73.244,68.407 73.205,68.446 68.879,68.446 68.879,75.857 72.153,75.857 72.153,80.452 68.879,80.452 68.879,83.552 73.153,83.552 73.153,88.475 73.068,88.56 68.879,88.56 68.879,96.602 73.175,96.602 73.175,101.746 73.122,101.799 68.778,101.799 68.778,108.854 79.403,108.854
S_LS_P1 on Top Layer "TOP_LAYER_S_LS_P1_P110" (solid, remove dead copper, pour order 110): 119.505,49.517 113.005,49.517 113.005,54.08 113.346,54.421 113.346,55.189 113.308,55.228 108.981,55.228 108.981,63.517 113.346,63.517 113.346,68.472 113.308,68.511 108.981,68.511 108.981,75.922 112.255,75.922 112.255,80.517 108.981,80.517 108.981,83.617 113.255,83.617 113.255,88.54 113.17,88.625 108.981,88.625 108.981,96.667 113.278,96.667 113.278,101.811 113.225,101.864 108.88,101.864 108.88,108.92 119.505,108.92
+5V_P1 on Top Layer "TOP_LAYER_+5V_P1_P054" (solid, remove dead copper, pour order 54): 86.25,126.25 87.25,126.25 87.25,123.5 90,123.5 90,121.219 89.863,121.356 87.25,121.356 87.25,122.16 83.75,122.16 83.75,123.5 86.25,123.5
NetC3_P3_2 on L3 "L3_NETC3_P3_2_P055" (solid, remove dead copper, pour order 55): 0.647,128.275 11.876,128.275 11.876,111.75 0.647,111.75
NetC3_P2_2 on L3 "L3_NETC3_P2_2_P056" (solid, remove dead copper, pour order 56): 40.647,128.275 51.876,128.275 51.876,111.75 40.647,111.75
NetC3_P1_2 on L3 "L3_NETC3_P1_2_P057" (solid, remove dead copper, pour order 57): 80.647,128.275 91.876,128.275 91.876,111.75 80.647,111.75
NetJ1_P3_1 on L3 "L3_NETJ1_P3_1_P067" (solid, remove dead copper, pour order 67): 37.5,145.011 37.5,120.75 23.5,120.75 23.5,120.95 23.5,145.011
NetJ1_P2_1 on L3 "L3_NETJ1_P2_1_P068" (solid, remove dead copper, pour order 68): 77.5,145.011 77.5,120.75 63.5,120.75 63.5,120.95 63.5,145.011
NetJ1_P1_1 on L3 "L3_NETJ1_P1_1_P069" (solid, remove dead copper, pour order 69): 117.5,145.011 117.5,120.75 103.5,120.75 103.5,120.95 103.5,145.011
D_HS_P1 on L3 "L3_D_HS_P1_P082" (solid, remove dead copper, pour order 82): 0.75,110 11.876,110 11.876,109.982 11.876,21.768 11.876,21.75 0.75,21.75
D_HS_P1 on L3 "L3_D_HS_P1_P083" (solid, remove dead copper, pour order 83): 40.75,110 51.876,110 51.876,109.982 51.876,21.768 51.876,21.75 40.75,21.75
D_HS_P1 on L3 "L3_D_HS_P1_P084" (solid, remove dead copper, pour order 84): 80.75,110 91.876,110 91.876,109.982 91.876,21.768 91.876,21.75 80.75,21.75
S_LS_P1 on L3 "L3_S_LS_P1_P088" (solid, remove dead copper, pour order 88): 28.876,109 39.5,109 39.5,21.75 28.876,21.75
S_LS_P1 on L3 "L3_S_LS_P1_P089" (solid, remove dead copper, pour order 89): 68.876,109 79.5,109 79.5,21.75 68.876,21.75
S_LS_P1 on L3 "L3_S_LS_P1_P090" (solid, remove dead copper, pour order 90): 108.876,109 119.25,109 119.25,21.75 108.876,21.75
D_LS_P3 on L3 "L3_D_LS_P3_P094" (solid, remove dead copper, pour order 94): 37.5,119.75 37.5,109.5 28.717,109.5 26.75,107.533 26.75,52.25 14.25,52.25 14.25,113.75 20.25,119.75 21.626,119.75
D_LS_P2 on L3 "L3_D_LS_P2_P095" (solid, remove dead copper, pour order 95): 77.5,119.75 77.5,109.5 68.717,109.5 66.75,107.533 66.75,52.25 54.25,52.25 54.25,113.75 60.25,119.75 61.626,119.75
D_LS_P1 on L3 "L3_D_LS_P1_P096" (solid, remove dead copper, pour order 96): 117.5,119.75 117.5,109.5 108.717,109.5 106.75,107.533 106.75,52.25 94.25,52.25 94.25,113.75 100.25,119.75 101.626,119.75
S_LS_P1 on L3 "L3_S_LS_P1_P105" (solid, remove dead copper, pour order 105): 0.75,49.25 118.5,49.25 118.5,2 0.853,2 0.845,1.992
NetC3_P3_2 on Bottom Layer "BOTTOM_LAYER_NETC3_P3_2_P058" (solid, remove dead copper, pour order 58): 0.647,128.275 11.876,128.275 11.876,111.75 0.647,111.75
NetC3_P2_2 on Bottom Layer "BOTTOM_LAYER_NETC3_P2_2_P059" (solid, remove dead copper, pour order 59): 40.647,128.275 51.876,128.275 51.876,111.75 40.647,111.75
NetC3_P1_2 on Bottom Layer "BOTTOM_LAYER_NETC3_P1_2_P060" (solid, remove dead copper, pour order 60): 80.647,128.275 91.876,128.275 91.876,111.75 80.647,111.75
NetJ1_P3_1 on Bottom Layer "BOTTOM_LAYER_NETJ1_P3_1_P070" (solid, remove dead copper, pour order 70): 37.5,145 37.5,120.739 23.5,120.739 23.5,120.939 23.5,145
NetJ1_P2_1 on Bottom Layer "BOTTOM_LAYER_NETJ1_P2_1_P071" (solid, remove dead copper, pour order 71): 77.5,145 77.5,120.739 63.5,120.739 63.5,120.939 63.5,145
NetJ1_P1_1 on Bottom Layer "BOTTOM_LAYER_NETJ1_P1_1_P072" (solid, remove dead copper, pour order 72): 117.5,145 117.5,120.739 103.5,120.739 103.5,120.939 103.5,145
D_HS_P1 on Bottom Layer "BOTTOM_LAYER_D_HS_P1_P085" (solid, remove dead copper, pour order 85): 0.75,110 11.876,110 11.876,109.982 11.876,21.768 11.876,21.75 0.75,21.75
D_HS_P1 on Bottom Layer "BOTTOM_LAYER_D_HS_P1_P086" (solid, remove dead copper, pour order 86): 40.75,110 51.876,110 51.876,109.982 51.876,21.768 51.876,21.75 40.75,21.75
D_HS_P1 on Bottom Layer "BOTTOM_LAYER_D_HS_P1_P087" (solid, remove dead copper, pour order 87): 80.75,110 91.876,110 91.876,109.982 91.876,21.768 91.876,21.75 80.75,21.75
S_LS_P1 on Bottom Layer "BOTTOM_LAYER_S_LS_P1_P091" (solid, remove dead copper, pour order 91): 28.876,109 39.5,109 39.5,21.75 28.876,21.75
S_LS_P1 on Bottom Layer "BOTTOM_LAYER_S_LS_P1_P092" (solid, remove dead copper, pour order 92): 68.876,109 79.5,109 79.5,21.75 68.876,21.75
S_LS_P1 on Bottom Layer "BOTTOM_LAYER_S_LS_P1_P093" (solid, remove dead copper, pour order 93): 108.876,109 119.25,109 119.25,21.75 108.876,21.75
D_LS_P3 on Bottom Layer "BOTTOM_LAYER_D_LS_P3_P097" (solid, remove dead copper, pour order 97): 37.5,119.75 37.5,109.5 28.717,109.5 26.75,107.533 26.75,52.25 14.25,52.25 14.25,113.75 20.25,119.75 21.626,119.75
D_LS_P2 on Bottom Layer "BOTTOM_LAYER_D_LS_P2_P098" (solid, remove dead copper, pour order 98): 77.5,119.75 77.5,109.5 68.717,109.5 66.75,107.533 66.75,52.25 54.25,52.25 54.25,113.75 60.25,119.75 61.626,119.75
D_LS_P1 on Bottom Layer "BOTTOM_LAYER_D_LS_P1_P099" (solid, remove dead copper, pour order 99): 117.5,119.75 117.5,109.5 108.717,109.5 106.75,107.533 106.75,52.25 94.25,52.25 94.25,113.75 100.25,119.75 101.626,119.75
S_LS_P1 on Bottom Layer "BOTTOM_LAYER_S_LS_P1_P106" (solid, remove dead copper, pour order 106): 0.5,49.25 119.25,49.25 119.25,2 0.603,2 0.595,1.992

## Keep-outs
Keep-Out Layer:
  text ".Layer_Name" at 14.656,-21.806 h1.52

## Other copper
Top Layer:
  text ".Layer_Name" at 14.656,-21.806 h1.52
Bottom Layer:
  text ".Layer_Name" at 14.656,-21.806 h1.52

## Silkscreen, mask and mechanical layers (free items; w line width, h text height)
Top Overlay:
  text "U" at 15.5,136.34 h7.5
  text "V" at 55.5,136.25 h7.5
  text "W" at 95.5,136.25 h7.5
  text "-" at 69.5,7.773 h7.5
  text "+" at 28,6.806 h7.5
  text "'.PRJ_Number'.PCB_Rev" at 94.5,5.961 h2.75
  text ".Layer_Name" at 14.656,-21.806 h1.52
Bottom Overlay:
  text ".Layer_Name" at 14.656,-21.806 h1.52
Top Paste:
  text ".Layer_Name" at 14.656,-21.806 h1.52
Bottom Paste:
  text ".Layer_Name" at 14.656,-21.806 h1.52
Top Solder:
  text ".Layer_Name" at 14.656,-21.806 h1.52
  text ".Layer_Name" at 14.656,-21.806 h1.52
Bottom Solder:
  rectangle: 0.75,49.5 119.25,110
  text ".Layer_Name" at 14.656,-21.806 h1.52
Drill Guide:
  text ".Layer_Name" at 14.656,-21.806 h1.52
M1 Board Outline:
  the board outline again, w0.254
  text ".Layer_Name" at 14.656,-21.806 h1.52
M2 Board Dimensions:
  rectangle: 0,-6.985 3.175,-3.81
  rectangle: 3.175,-10.16 12.7,-6.985
  lines w0.178: 0,-6.985 25.4,-6.985 ; 3.175,-10.16 3.175,-3.81 ; 6.35,-10.16 6.35,-3.81 ; 12.7,-10.16 12.7,-3.81 ; 19.05,-10.16 19.05,-3.81 ; 0,-10.16 25.4,-10.16 25.4,-3.81 0,-3.81 0,-10.16
  text ".Layer_Name" at 14.656,-21.806 h1.52
M3 3D STEP Top:
  text ".Layer_Name" at 14.656,-21.806 h1.52
M4 3D STEP Bottom:
  text ".Layer_Name" at 14.656,-21.806 h1.52
M5 Assembly Top:
  lines w0.254: -7.417,-23.626 160.223,-23.626 ; -7.417,-18.462 160.274,-18.462 ; -7.417,-13.297 -7.417,-28.791 94.31,-28.791 160.274,-28.791 160.274,-13.297 -7.404,-13.297 -7.404,-28.791 32.614,-28.791 ; 55.194,-28.791 55.194,-13.297 ; 87.376,-18.462 87.376,-13.297 ; 108.712,-18.462 108.712,-13.297 ; 124.511,-28.956 124.511,-23.804
  text "COMPONENTS MARKED 'DNP' SHOULD NOT BE POPULATED." at 29.299,-8.09 h1.52
  text "ASSEMBLY VARIANT:" at 29.286,-11.024 h1.52
  text ".VariantName" at 55.601,-11.024 h1.52
  text "PCB VIEWED FROM TOP SIDE" at -5.804,-16.654 h1.52
  text "BOARD #:" at 57.099,-16.654 h1.52
  text ".PRJ_Number" at 70.955,-16.654 h1.52
  text "REV:" at 92.405,-16.654 h1.52
  text ".PCB_Rev" at 99.809,-16.654 h1.52
  text "SVN REV:" at 113.69,-16.654 h1.52
  text ".VersionControl_RevNumber" at 126.543,-16.654 h1.52
  text "TID #:" at 57.099,-21.819 h1.52
  text ".TID" at 70.955,-21.819 h1.52
  text "PLOT NAME =" at -5.804,-27.034 h1.52
  text ".plot_File_Name" at 14.656,-27.034 h1.52
  text "GENERATED    :" at 57.15,-27.034 h1.52
  text ".Print_Date" at 79.235,-27.034 h1.52
  text ".Print_Time" at 97.752,-27.034 h1.52
  text "TEXAS INSTRUMENTS" at 129.87,-27.034 h1.52
M6 Assembly Bottom:
  lines w0.254: -7.429,-18.474 160.261,-18.474 ; -7.379,-23.639 160.261,-23.639 ; 28.334,-28.969 28.334,-23.817 ; 44.133,-18.474 44.133,-13.31 ; 65.468,-18.474 65.468,-13.31 ; 97.65,-28.804 97.65,-13.31 ; 120.231,-28.804 160.249,-28.804 160.249,-13.31 -7.429,-13.31 -7.429,-28.804 58.534,-28.804 160.261,-28.804 160.261,-13.31
  text "COMPONENTS MARKED 'DNP' SHOULD NOT BE POPULATED." at 154.991,-8.077 h1.52
  text ".VariantName" at 128.473,-11.024 h1.52
  text "ASSEMBLY VARIANT:" at 154.864,-11.024 h1.52
  text ".VersionControl_RevNumber" at 26.302,-16.667 h1.52
  text "SVN REV:" at 39.154,-16.667 h1.52
  text ".PCB_Rev" at 53.035,-16.667 h1.52
  text "REV:" at 60.439,-16.667 h1.52
  text ".PRJ_Number" at 81.89,-16.667 h1.52
  text "BOARD #:" at 95.745,-16.667 h1.52
  text "PCB VIEWED FROM BOTTOM SIDE" at 158.648,-16.667 h1.52
  text ".TID" at 81.89,-21.831 h1.52
  text "TID #:" at 95.745,-21.831 h1.52
  text "TEXAS INSTRUMENTS" at 22.974,-27.047 h1.52
  text ".Print_Time" at 55.093,-27.047 h1.52
  text ".Print_Date" at 73.609,-27.047 h1.52
  text "GENERATED    :" at 95.694,-27.047 h1.52
  text ".plot_File_Name" at 138.189,-27.047 h1.52
  text "PLOT NAME =" at 158.648,-27.047 h1.52
M9 Title Sheet:
  drawing of 56 lines, arcs and shapes, not listed
  text "1" at 18.792,204.127 h1.78
  text "2" at 82.182,204.127 h1.78
  text "3" at 145.411,204.127 h1.78
  text "4" at 209.08,204.127 h1.78
  text "5" at 272.555,204.127 h1.78
  text "6" at 336.182,204.127 h1.78
  text "A" at -10.579,175.095 h1.78
  text "A" at 365.341,175.095 h1.78
  text "B" at -10.579,114.643 h1.78
  text "B" at 365.341,114.643 h1.78
  text "C" at -10.579,54.318 h1.78
  text "C" at 365.341,54.318 h1.78
  text "PROJECT TITLE:" at 288.125,7.048 h1.14
  text ".PRJ_Title" at 289.395,3.662 h1.78
  text "DESIGNED FOR:" at 288.125,-0.597 h1.14
  text ".PRJ_Customer" at 289.395,-4.153 h1.78
  text "D" at -10.579,-5.88 h1.78
  text "D" at 365.341,-5.88 h1.78
  text "FILE NAME:" at 288.125,-8.217 h1.14
  text ".PCB_File_Name_No_Path" at 289.395,-11.265 h1.78
  text "Texas Instruments (TI) and/or its licensors do not warrant the accuracy or completeness of this specification" at 161.9,-15.376 h1.14
  text "ENGINEER:" at 288.125,-15.583 h1.14
  text "LAYOUT BY:" at 326.352,-15.583 h1.14
  text "or any information contained therein. TI and/or its licensors do not warrant that this design will meet" at 160.757,-18.237 h1.14
  text ".PRJ_Engineer" at 289.395,-19.52 h1.78
  text ".PCB_Layout" at 327.635,-19.52 h1.78
  text "the specifications, will be suitable for your application or fit for any particular purpose, or will operate in" at 160.757,-21.099 h1.14
  text ".Layer_Name" at 14.656,-21.806 h1.52
  text "ALTIUM DESIGNER VERSION:" at 326.352,-23.457 h1.14
  text "an implementation. TI and/or its licensors do not warrant that the design is production worthy. You should" at 160.757,-23.961 h1.14
  text "completely validate and test your design implementation to confirm the system functionality for your application." at 161.9,-26.822 h1.14
  text ".print_Scale" at 289.395,-26.843 h1.78
  text ".Application_BuildNumber" at 327.635,-26.843 h1.78
  text "1" at 18.792,-32.093 h1.78
  text "2" at 82.182,-32.093 h1.78
  text "3" at 145.411,-32.093 h1.78
  text "4" at 209.08,-32.093 h1.78
  text "5" at 272.555,-32.093 h1.78
  text "6" at 336.182,-32.093 h1.78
